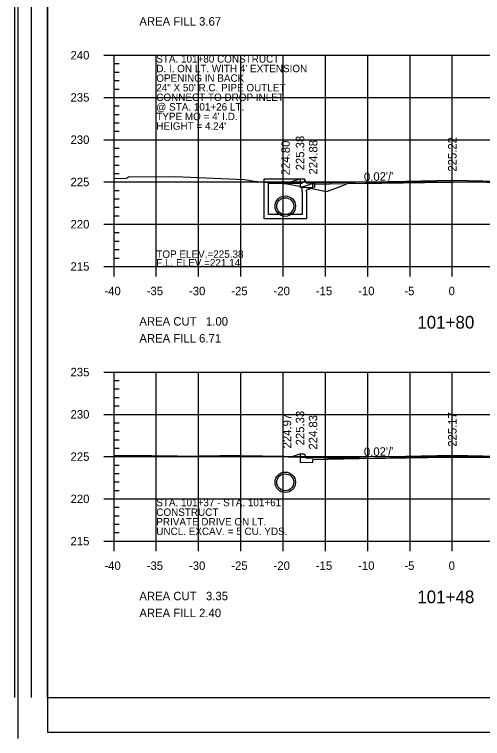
# Model space of a CAD drawing. Extents: x 1367903 to 1373764, y 376865 to 382130.
# Drawn here: x 1369975.7 to 1370086.4, y 377279.1 to 377450.5 of the extents above; entities that cross this region are included whole.
import ezdxf

# ---------------------------------------------------------------- set-up
doc = ezdxf.new("R2010")
doc.units = 0
for name, color, linetype in [('R_Axis', 7, 'Continuous'), ('R_Axis Annot', 7, 'Continuous'), ('R_Border', 7, 'Continuous'), ('R_Border PE', 7, 'Continuous'), ('R_Draft', 7, 'Continuous'), ('R_Drive', 7, 'Continuous'), ('R_Exist Surface', 7, 'Continuous'), ('R_Fin Surface', 7, 'Continuous'), ('R_Fin Surface Annot', 7, 'Continuous'), ('R_Grid', 7, 'Continuous'), ('R_Water', 7, 'Continuous'), ('R_Water Annot', 7, 'Continuous')]:
    doc.layers.add(name, color=color, linetype=linetype)

msp = doc.modelspace()

# ---------------------------------------------------------------- linework, layer by layer
for p, q in [((1370034.72, 377411.59), (1370044.22, 377411.59)), ((1370034.72, 377408.59), (1370034.72, 377411.59)), ((1370035.72, 377408.59), (1370035.72, 377410.59)), ((1370035.72, 377410.59), (1370043.72, 377410.59)), ((1370044.39, 377411.26), (1370043.72, 377410.59)), ((1370046.72, 377410.63), (1370043.72, 377409.59)), ((1370044.39, 377411.26), (1370044.22, 377411.59)), ((1370043.72, 377408.59), (1370043.72, 377409.59)), ((1370046.72, 377409.57), (1370044.72, 377408.88)), ((1370044.72, 377408.59), (1370044.72, 377408.88))]:
    msp.add_line(p, q)
for points in [[(1370043.22, 377411.59), (1370043.22, 377410.92), (1370043.22, 377410.92), (1370043.22, 377409.56), (1370046.22, 377409.62), (1370046.22, 377410.29), (1370079.22, 377410.95), (1370112.22, 377410.29), (1370112.22, 377409.62), (1370115.22, 377409.56), (1370115.22, 377411), (1370129.22, 377411.28), (1370129.22, 377411.87)], [(1370046.72, 377409.57), (1370046.72, 377410.63)], [(1370043.22, 377346.49), (1370043.22, 377345.82), (1370043.22, 377345.82), (1370043.22, 377344.46), (1370046.22, 377344.52), (1370046.22, 377345.18), (1370079.22, 377345.84), (1370112.22, 377345.18), (1370112.22, 377344.52), (1370115.22, 377344.46), (1370115.22, 377345.9), (1370129.22, 377346.18), (1370129.22, 377346.77)]]:
    msp.add_lwpolyline(points)
at = {"layer": 'R_Axis'}
for p, q in [((1369996.82, 377440.84), (1370001.62, 377440.84)), ((1369999.22, 377390.84), (1369999.22, 377440.84)), ((1369999.22, 377438.84), (1370000.42, 377438.84)), ((1369999.22, 377436.84), (1370000.42, 377436.84)), ((1369999.22, 377434.84), (1370000.42, 377434.84)), ((1369999.22, 377432.84), (1370000.42, 377432.84)), ((1369996.82, 377430.84), (1370001.62, 377430.84)), ((1369999.22, 377428.84), (1370000.42, 377428.84)), ((1369999.22, 377426.84), (1370000.42, 377426.84)), ((1369999.22, 377424.84), (1370000.42, 377424.84)), ((1369999.22, 377422.84), (1370000.42, 377422.84)), ((1369996.82, 377420.84), (1370001.62, 377420.84)), ((1369999.22, 377418.84), (1370000.42, 377418.84)), ((1369999.22, 377416.84), (1370000.42, 377416.84)), ((1369999.22, 377414.84), (1370000.42, 377414.84)), ((1369999.22, 377412.84), (1370000.42, 377412.84)), ((1369996.82, 377410.84), (1370001.62, 377410.84)), ((1369999.22, 377408.84), (1370000.42, 377408.84)), ((1369999.22, 377406.84), (1370000.42, 377406.84)), ((1369999.22, 377404.84), (1370000.42, 377404.84)), ((1369999.22, 377402.84), (1370000.42, 377402.84)), ((1369996.82, 377400.84), (1370001.62, 377400.84)), ((1369999.22, 377398.84), (1370000.42, 377398.84)), ((1369999.22, 377396.84), (1370000.42, 377396.84)), ((1369999.22, 377394.84), (1370000.42, 377394.84)), ((1369999.22, 377388.44), (1369999.22, 377393.24)), ((1370009.22, 377388.44), (1370009.22, 377393.24)), ((1370019.22, 377388.44), (1370019.22, 377393.24)), ((1370029.22, 377388.44), (1370029.22, 377393.24)), ((1370039.22, 377388.44), (1370039.22, 377393.24)), ((1370049.22, 377388.44), (1370049.22, 377393.24)), ((1370059.22, 377388.44), (1370059.22, 377393.24)), ((1370069.22, 377388.44), (1370069.22, 377393.24)), ((1370079.22, 377388.44), (1370079.22, 377393.24)), ((1369999.22, 377392.84), (1370000.42, 377392.84)), ((1369996.82, 377390.84), (1370001.62, 377390.84)), ((1369999.22, 377390.84), (1370159.22, 377390.84)), ((1369996.82, 377365.84), (1370001.62, 377365.84)), ((1369999.22, 377325.84), (1369999.22, 377365.84)), ((1369999.22, 377363.84), (1370000.42, 377363.84)), ((1369999.22, 377361.84), (1370000.42, 377361.84)), ((1369999.22, 377359.84), (1370000.42, 377359.84)), ((1369999.22, 377357.84), (1370000.42, 377357.84)), ((1369996.82, 377355.84), (1370001.62, 377355.84)), ((1369999.22, 377353.84), (1370000.42, 377353.84)), ((1369999.22, 377351.84), (1370000.42, 377351.84)), ((1369999.22, 377349.84), (1370000.42, 377349.84)), ((1369999.22, 377347.84), (1370000.42, 377347.84)), ((1369996.82, 377345.84), (1370001.62, 377345.84)), ((1369999.22, 377343.84), (1370000.42, 377343.84)), ((1369999.22, 377341.84), (1370000.42, 377341.84)), ((1369999.22, 377339.84), (1370000.42, 377339.84)), ((1369999.22, 377337.84), (1370000.42, 377337.84)), ((1369996.82, 377335.84), (1370001.62, 377335.84)), ((1369999.22, 377333.84), (1370000.42, 377333.84)), ((1369999.22, 377331.84), (1370000.42, 377331.84)), ((1369999.22, 377329.84), (1370000.42, 377329.84)), ((1369999.22, 377323.44), (1369999.22, 377328.24)), ((1369999.22, 377327.84), (1370000.42, 377327.84)), ((1370009.22, 377323.44), (1370009.22, 377328.24)), ((1370019.22, 377323.44), (1370019.22, 377328.24)), ((1370029.22, 377323.44), (1370029.22, 377328.24)), ((1370039.22, 377323.44), (1370039.22, 377328.24)), ((1370049.22, 377323.44), (1370049.22, 377328.24)), ((1370059.22, 377323.44), (1370059.22, 377328.24)), ((1370069.22, 377323.44), (1370069.22, 377328.24)), ((1370079.22, 377323.44), (1370079.22, 377328.24)), ((1369996.82, 377325.84), (1370001.62, 377325.84)), ((1369999.22, 377325.84), (1370159.22, 377325.84))]:
    msp.add_line(p, q, dxfattribs=at)
at = {"layer": 'R_Border'}
for p, q in [((1369976.49, 377620.35), (1369976.49, 377279.12)), ((1369983.52, 377611.47), (1369983.52, 377280.59)), ((1369983.52, 377280.59), (1370187.85, 377280.59))]:
    msp.add_line(p, q, dxfattribs=at)
at = {"layer": 'R_Border PE'}
for p, q in [((1369975.69, 377610.76), (1369975.69, 377288.8)), ((1369979.6, 377610.76), (1369979.6, 377288.8)), ((1369983.52, 377288.8), (1369983.52, 377603.25)), ((1369983.52, 377288.8), (1370187.85, 377288.8))]:
    msp.add_line(p, q, dxfattribs=at)
at = {"layer": 'R_Drive'}
for q in [(1370019.22, 377345.96), (1370044.55, 377345.83)]:
    msp.add_line((1370029.22, 377346.13), q, dxfattribs=at)
at = {"layer": 'R_Exist Surface'}
for points in [[(1369999.22, 377411.67), (1370002.15, 377411.76), (1370002.62, 377412.06), (1370013.69, 377412.14), (1370028.18, 377411.51), (1370030.06, 377411.44), (1370032.34, 377411.01), (1370035.74, 377410.69), (1370040.16, 377410.42), (1370045.99, 377409.3), (1370049.48, 377408.57), (1370053.17, 377409.91), (1370054.59, 377410.57), (1370056.15, 377410.54), (1370057.51, 377410.5), (1370072.75, 377410.69), (1370085.29, 377410.84), (1370097.45, 377410.62), (1370115.65, 377410.34), (1370115.9, 377410.39), (1370115.92, 377410.41), (1370121.47, 377410.47), (1370154.8, 377410.86), (1370159.22, 377410.81)], [(1369999.22, 377346.18), (1370008.12, 377346.07), (1370026.5, 377345.88), (1370037.69, 377345.88), (1370046.02, 377345.63), (1370048.84, 377345.53), (1370054.49, 377345.44), (1370057.25, 377345.5), (1370058.38, 377345.42), (1370073.41, 377345.6), (1370084.91, 377345.72), (1370110.8, 377345.53), (1370116.14, 377345.47), (1370116.28, 377345.51), (1370116.81, 377345.58), (1370118.44, 377345.62), (1370118.67, 377345.64), (1370124.46, 377345.77), (1370153.77, 377345.86), (1370159.22, 377345.87)]]:
    msp.add_lwpolyline(points, dxfattribs=at)
at = {"layer": 'R_Fin Surface'}
for points in [[(1370039.78, 377410.44), (1370043.22, 377411.59), (1370044.22, 377411.59), (1370044.72, 377410.59), (1370046.22, 377410.62), (1370068.22, 377411.06), (1370079.22, 377411.28), (1370090.22, 377411.06), (1370112.22, 377410.62), (1370113.72, 377410.59), (1370114.22, 377411.59), (1370115.22, 377411.59), (1370119.22, 377411.67), (1370129.22, 377411.87), (1370133.02, 377410.6)], [(1370041.09, 377345.78), (1370043.22, 377346.49), (1370044.22, 377346.49), (1370044.72, 377345.49), (1370046.22, 377345.52), (1370068.22, 377345.96), (1370079.22, 377346.18), (1370090.22, 377345.96), (1370112.22, 377345.52), (1370113.72, 377345.49), (1370114.22, 377346.49), (1370115.22, 377346.49), (1370119.22, 377346.57), (1370129.22, 377346.77), (1370132.13, 377345.8)]]:
    msp.add_lwpolyline(points, dxfattribs=at)
at = {"layer": 'R_Grid'}
for p, q in [((1369999.22, 377440.84), (1370159.22, 377440.84)), ((1369999.22, 377390.84), (1369999.22, 377440.84)), ((1370009.22, 377390.84), (1370009.22, 377440.84)), ((1370019.22, 377390.84), (1370019.22, 377440.84)), ((1370029.22, 377390.84), (1370029.22, 377440.84)), ((1370039.22, 377390.84), (1370039.22, 377440.84)), ((1370049.22, 377390.84), (1370049.22, 377440.84)), ((1370059.22, 377390.84), (1370059.22, 377440.84)), ((1370069.22, 377390.84), (1370069.22, 377440.84)), ((1370079.22, 377390.84), (1370079.22, 377440.84)), ((1369999.22, 377430.84), (1370159.22, 377430.84)), ((1369999.22, 377420.84), (1370159.22, 377420.84)), ((1369999.22, 377410.84), (1370159.22, 377410.84)), ((1369999.22, 377400.84), (1370159.22, 377400.84)), ((1369999.22, 377390.84), (1370159.22, 377390.84)), ((1369999.22, 377365.84), (1370159.22, 377365.84)), ((1369999.22, 377325.84), (1369999.22, 377365.84)), ((1370009.22, 377325.84), (1370009.22, 377365.84)), ((1370019.22, 377325.84), (1370019.22, 377365.84)), ((1370029.22, 377325.84), (1370029.22, 377365.84)), ((1370039.22, 377325.84), (1370039.22, 377365.84)), ((1370049.22, 377325.84), (1370049.22, 377365.84)), ((1370059.22, 377325.84), (1370059.22, 377365.84)), ((1370069.22, 377325.84), (1370069.22, 377365.84)), ((1370079.22, 377325.84), (1370079.22, 377365.84)), ((1369999.22, 377355.84), (1370159.22, 377355.84)), ((1369999.22, 377345.84), (1370159.22, 377345.84)), ((1369999.22, 377335.84), (1370159.22, 377335.84)), ((1369999.22, 377325.84), (1370159.22, 377325.84))]:
    msp.add_line(p, q, dxfattribs=at)
at = {"layer": 'R_Water'}
for p, q in [((1370039.72, 377342.2), (1370039.72, 377342.15)), ((1370039.72, 377341.78), (1370039.72, 377341.74)), ((1370039.72, 377337.78), (1370039.72, 377337.74)), ((1370039.72, 377337.37), (1370039.72, 377337.32))]:
    msp.add_line(p, q, dxfattribs=at)
for points in [[(1370044.72, 377408.59), (1370044.72, 377402.12), (1370039.72, 377402.12), (1370034.72, 377402.12), (1370034.72, 377408.59)], [(1370043.72, 377408.59), (1370043.72, 377403.12), (1370039.72, 377403.12), (1370035.72, 377403.12), (1370035.72, 377408.59)]]:
    msp.add_lwpolyline(points, dxfattribs=at)
for centre, radius in [((1370039.72, 377405.12), 2.42), ((1370039.72, 377405.12), 2.42), ((1370039.72, 377405.12), 2), ((1370039.72, 377405.12), 2), ((1370039.72, 377339.76), 2.42), ((1370039.72, 377339.76), 2)]:
    msp.add_circle(centre, radius, dxfattribs=at)

# ---------------------------------------------------------------- texts
at = {"layer": 'R_Axis Annot'}
for s, height, p in [('AREA FILL 3.67', 2, (1370005.22, 377447.84)), ('240', 2, (1369988.94, 377439.84)), ('235', 2, (1369988.94, 377429.84)), ('230', 2, (1369988.94, 377419.84)), ('225', 2, (1369988.94, 377409.84)), ('220', 2, (1369988.94, 377399.84)), ('215', 2, (1369988.94, 377389.84)), ('-40', 2, (1369996.95, 377384.04)), ('-35', 2, (1370006.95, 377384.04)), ('-30', 2, (1370016.95, 377384.04)), ('-25', 2, (1370026.95, 377384.04)), ('-20', 2, (1370036.95, 377384.04)), ('-15', 2, (1370046.95, 377384.04)), ('-10', 2, (1370056.95, 377384.04)), ('-5', 2, (1370067.88, 377384.04)), ('0', 2, (1370078.35, 377384.04)), ('AREA CUT   1.00', 2, (1370005.22, 377376.84)), ('101+80', 3, (1370070.93, 377376.14)), ('AREA FILL 6.71', 2, (1370005.22, 377372.84)), ('235', 2, (1369988.94, 377364.84)), ('230', 2, (1369988.94, 377354.84)), ('225', 2, (1369988.94, 377344.84)), ('220', 2, (1369988.94, 377334.84)), ('215', 2, (1369988.94, 377324.84)), ('-40', 2, (1369996.95, 377319.04)), ('-35', 2, (1370006.95, 377319.04)), ('-30', 2, (1370016.95, 377319.04)), ('-25', 2, (1370026.95, 377319.04)), ('-20', 2, (1370036.95, 377319.04)), ('-15', 2, (1370046.95, 377319.04)), ('-10', 2, (1370056.95, 377319.04)), ('-5', 2, (1370067.88, 377319.04)), ('0', 2, (1370078.35, 377319.04)), ('101+48', 3, (1370070.93, 377311.14)), ('AREA CUT   3.35', 2, (1370005.22, 377311.84)), ('AREA FILL 2.40', 2, (1370005.22, 377307.84))]:
    msp.add_text(s, height=height, dxfattribs=at).set_placement(p)
at = {"layer": 'R_Draft'}
for s, p in [('STA. 101+80 CONSTRUCT', (1370009.22, 377439.09)), ("D. I. ON LT. WITH 4' EXTENSION", (1370009.22, 377436.82)), ('OPENING IN BACK', (1370009.22, 377434.55)), ('24" X 50\' R.C. PIPE OUTLET', (1370009.22, 377432.28)), ('CONNECT TO DROP INLET', (1370009.22, 377430.01)), ('@ STA. 101+26 LT.', (1370009.22, 377427.74)), ("TYPE MO = 4' I.D.", (1370009.22, 377425.47)), ("HEIGHT = 4.24'", (1370009.22, 377423.2)), ('STA. 101+37 - STA. 101+61', (1370009.22, 377334.09)), ('CONSTRUCT', (1370009.22, 377331.82)), ('PRIVATE DRIVE ON LT.', (1370009.22, 377329.55)), ('UNCL. EXCAV. = 5 CU. YDS.', (1370009.22, 377327.28))]:
    msp.add_text(s, height=1.75, dxfattribs=at).set_placement(p)
at = {"layer": 'R_Fin Surface Annot'}
for s, rotation, p in [('224.80', 90, (1370040.78, 377412.44)), ('225.38', 90, (1370044.22, 377413.59)), ('224.88', 90, (1370047.32, 377412.59)), ('225.22', 90, (1370080.22, 377413.28)), ("0.02'/'", 1.1458, (1370058.34, 377411.06)), ('224.97', 90, (1370041.13, 377347.78)), ('225.33', 90, (1370044.22, 377348.49)), ('224.83', 90, (1370047.28, 377347.49)), ('225.17', 90, (1370080.22, 377348.18)), ("0.02'/'", 1.1458, (1370058.34, 377345.96))]:
    msp.add_text(s, height=2, rotation=rotation, dxfattribs=at).set_placement(p)
at = {"layer": 'R_Water Annot'}
for s, p in [('TOP ELEV.=225.38', (1370009.22, 377392.89)), ('F.L. ELEV.=221.14', (1370009.22, 377390.84))]:
    msp.add_text(s, height=1.75, dxfattribs=at).set_placement(p)

doc.saveas('drawing.dxf')
